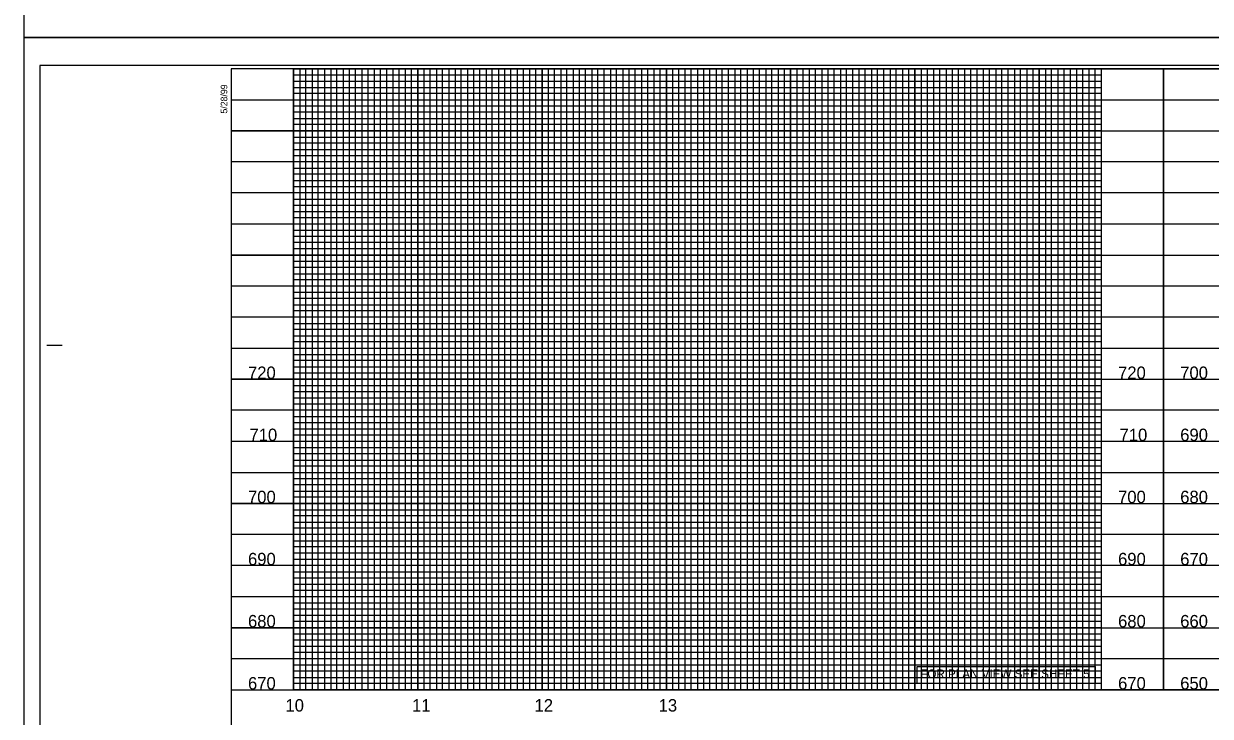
# Model space of a CAD drawing. Extents: x 1754992 to 1757273, y 732111 to 735411.
# Drawn here: x 1755181 to 1756135, y 732664 to 733222 of the extents above; entities that cross this region are included whole.
import ezdxf

# ---------------------------------------------------------------- set-up
doc = ezdxf.new("R2010")
doc.units = 0
for name, color, linetype in [('ENG SEALS CELL', 7, 'Continuous'), ('Prop DSN Text', 7, 'Continuous'), ('Scratch_Level_3', 7, 'Continuous'), ('Sheet Cutting Line CELL', 7, 'Continuous'), ('Sheet DOT Grid CELL', 7, 'Continuous'), ('Sheet PE Seal Cell', 7, 'Continuous'), ('Sheet Plot Border Inside CELL', 7, 'Continuous'), ('Sheet Plot Border Outside CELL', 7, 'Continuous'), ('Sheet Profile CELL', 7, 'Continuous'), ('Sheet Profile Grid Major CELL', 7, 'Continuous'), ('Sheet Profile Grid Middle CELL', 7, 'Continuous'), ('Sheet Profile Grid Minor CELL', 7, 'Continuous')]:
    doc.layers.add(name, color=color, linetype=linetype)

msp = doc.modelspace()

# ---------------------------------------------------------------- linework, layer by layer
at = {"layer": 'ENG SEALS CELL'}
msp.add_lwpolyline([(1755899.57, 732704.63), (1756042.57, 732704.63), (1756042.57, 732690.9), (1755899.57, 732690.9)], close=True, dxfattribs=at)
at = {"layer": 'Scratch_Level_3'}
msp.add_lwpolyline([(1755397.67, 732685.78), (1755397.67, 733185.78), (1756647.62, 733185.78), (1756647.63, 732952.66), (1756797.67, 732952.66), (1756797.67, 732685.78)], close=True, dxfattribs=at)
at = {"layer": 'Sheet Cutting Line CELL'}
for p, q in [((1755180.67, 734310.78), (1755180.67, 733210.78)), ((1756864.67, 733210.78), (1755180.67, 733210.78)), ((1755180.67, 733210.78), (1755180.67, 732110.78)), ((1755180.67, 733210.78), (1756864.67, 733210.78))]:
    msp.add_line(p, q, dxfattribs=at)
at = {"layer": 'Sheet DOT Grid CELL'}
for p, q in [((1755397.67, 732685.78), (1755397.67, 733185.78)), ((1755447.67, 732685.78), (1755447.67, 733185.78)), ((1755497.67, 732685.78), (1755497.67, 733185.78)), ((1755547.67, 732685.78), (1755547.67, 733185.78)), ((1755597.67, 732685.78), (1755597.67, 733185.78)), ((1755647.67, 732685.78), (1755647.67, 733185.78)), ((1755697.67, 732685.78), (1755697.67, 733185.78)), ((1755747.67, 732685.78), (1755747.67, 733185.78)), ((1755797.67, 732685.78), (1755797.67, 733185.78)), ((1755847.67, 732685.78), (1755847.67, 733185.78)), ((1755897.67, 732685.78), (1755897.67, 733185.78)), ((1755947.67, 732685.78), (1755947.67, 733185.78)), ((1755997.67, 732685.78), (1755997.67, 733185.78)), ((1756047.67, 732685.78), (1756047.67, 733185.78)), ((1756097.67, 732685.78), (1756097.67, 733185.78)), ((1756047.68, 733135.78), (1755347.67, 733135.78)), ((1756047.68, 733085.78), (1755347.67, 733085.78)), ((1756047.68, 733035.78), (1755347.67, 733035.78)), ((1756047.68, 732985.78), (1755347.67, 732985.78)), ((1756047.68, 732935.78), (1755347.67, 732935.78)), ((1756047.68, 732885.78), (1755347.67, 732885.78)), ((1756047.68, 732835.78), (1755347.67, 732835.78)), ((1756047.68, 732785.78), (1755347.67, 732785.78)), ((1756047.68, 732735.78), (1755347.67, 732735.78))]:
    msp.add_line(p, q, dxfattribs=at)
at = {"layer": 'Sheet Plot Border Inside CELL'}
msp.add_lwpolyline([(1755193.67, 732133.23), (1756860.17, 732133.23), (1756860.17, 733188.33), (1755193.67, 733188.33)], close=True, dxfattribs=at)
at = {"layer": 'Sheet Plot Border Outside CELL'}
for points in [[(1755180.67, 733210.78), (1756864.67, 733210.78), (1756864.67, 734310.78), (1755180.67, 734310.78)], [(1755180.67, 732110.78), (1756864.67, 732110.78), (1756864.67, 733210.78), (1755180.67, 733210.78)]]:
    msp.add_lwpolyline(points, close=True, dxfattribs=at)
at = {"layer": 'Sheet Profile CELL'}
for p, q in [((1756097.67, 733185.78), (1756097.67, 732685.78)), ((1755199.17, 732963.28), (1755211.67, 732963.28)), ((1755347.67, 732685.78), (1756847.67, 732685.78))]:
    msp.add_line(p, q, dxfattribs=at)
msp.add_lwpolyline([(1756847.67, 733185.78), (1755347.67, 733185.78), (1755347.67, 732135.78), (1756847.67, 732135.78)], close=True, dxfattribs=at)
at = {"layer": 'Sheet Profile Grid Major CELL'}
for points in [[(1755397.67, 733185.78), (1755397.67, 732685.78), (1755447.67, 732685.78), (1755447.67, 733185.78), (1755497.67, 733185.78), (1755497.67, 732685.78), (1755547.67, 732685.78), (1755547.67, 733185.78), (1755597.67, 733185.78), (1755597.67, 732685.78), (1755647.67, 732685.78), (1755647.67, 733185.78), (1755697.67, 733185.78), (1755697.67, 732685.78), (1755747.67, 732685.78), (1755747.67, 733185.78), (1755797.67, 733185.78), (1755797.67, 732685.78), (1755847.67, 732685.78), (1755847.67, 733185.78), (1755897.67, 733185.78), (1755897.67, 732685.78), (1755947.67, 732685.78), (1755947.67, 733185.78), (1755997.67, 733185.78), (1755997.67, 732685.78), (1756047.67, 732685.78), (1756047.67, 733185.78), (1756097.67, 733185.78), (1756097.67, 732685.78), (1756147.67, 732685.78)], [(1755347.67, 733135.78), (1756647.67, 733135.78)], [(1756647.67, 733085.78), (1755347.67, 733085.78), (1755347.67, 733035.78), (1756647.67, 733035.78)], [(1756647.63, 732985.78), (1755347.67, 732985.78), (1755347.67, 732935.78), (1756847.67, 732935.78)], [(1756847.67, 732885.78), (1755347.67, 732885.78), (1755347.67, 732835.78), (1756847.67, 732835.78)], [(1756847.67, 732785.78), (1755347.67, 732785.78), (1755347.67, 732785.78), (1755347.67, 732735.78), (1756847.67, 732735.78)]]:
    msp.add_lwpolyline(points, dxfattribs=at)
at = {"layer": 'Sheet Profile Grid Middle CELL'}
for p, q in [((1755422.67, 733185.78), (1755422.67, 732685.78)), ((1755472.67, 732685.78), (1755472.67, 733185.78)), ((1755472.67, 733185.78), (1755522.67, 733185.78)), ((1755522.67, 733185.78), (1755522.67, 732685.78)), ((1755572.67, 732685.78), (1755572.67, 733185.78)), ((1755572.67, 733185.78), (1755622.67, 733185.78)), ((1755622.67, 733185.78), (1755622.67, 732685.78)), ((1755672.67, 732685.78), (1755672.67, 733185.78)), ((1755672.67, 733185.78), (1755722.67, 733185.78)), ((1755722.67, 733185.78), (1755722.67, 732685.78)), ((1755772.67, 732685.78), (1755772.67, 733185.78)), ((1755772.67, 733185.78), (1755822.67, 733185.78)), ((1755822.67, 733185.78), (1755822.67, 732685.78)), ((1755872.67, 732685.78), (1755872.67, 733185.78)), ((1755872.67, 733185.78), (1755922.67, 733185.78)), ((1755922.67, 733185.78), (1755922.67, 732685.78)), ((1755972.67, 732685.78), (1755972.67, 733185.78)), ((1755972.67, 733185.78), (1756022.67, 733185.78)), ((1756022.67, 733185.78), (1756022.67, 732685.78)), ((1756072.67, 733185.78), (1756122.67, 733185.78)), ((1755347.67, 733160.78), (1756647.62, 733160.78)), ((1755422.67, 732685.78), (1755472.67, 732685.78)), ((1755522.67, 732685.78), (1755572.67, 732685.78)), ((1755622.67, 732685.78), (1755672.67, 732685.78)), ((1755722.67, 732685.78), (1755772.67, 732685.78)), ((1755822.67, 732685.78), (1755872.67, 732685.78)), ((1755922.67, 732685.78), (1755972.67, 732685.78)), ((1755972.67, 732685.78), (1755972.67, 732685.78)), ((1756022.67, 732685.78), (1756072.67, 732685.78)), ((1756122.67, 732685.78), (1756172.67, 732685.78))]:
    msp.add_line(p, q, dxfattribs=at)
for points in [[(1756647.67, 733110.78), (1755347.67, 733110.78), (1755347.67, 733060.78), (1756647.67, 733060.78)], [(1756647.62, 733010.78), (1755347.67, 733010.78), (1755347.67, 732960.78), (1756647.63, 732960.78)], [(1756847.67, 732910.78), (1755347.67, 732910.78), (1755347.67, 732860.78), (1756847.67, 732860.78)], [(1756847.67, 732810.78), (1755347.67, 732810.78), (1755347.67, 732760.78), (1756847.67, 732760.78)], [(1756847.67, 732710.78), (1755347.67, 732710.78)]]:
    msp.add_lwpolyline(points, dxfattribs=at)
at = {"layer": 'Sheet Profile Grid Minor CELL'}
for p, q in [((1755397.67, 733180.78), (1756047.68, 733180.78)), ((1755927.67, 733185.78), (1755927.67, 732685.78)), ((1755932.67, 732685.78), (1755932.67, 733185.78)), ((1755932.67, 733185.78), (1755937.67, 733185.78)), ((1755937.67, 733185.78), (1755937.67, 732685.78)), ((1755942.67, 732685.78), (1755942.67, 733185.78)), ((1755942.67, 733185.78), (1755952.67, 733185.78)), ((1755952.67, 733185.78), (1755952.67, 732685.78)), ((1755957.67, 732685.78), (1755957.67, 733185.78)), ((1755957.67, 733185.78), (1755962.67, 733185.78)), ((1755962.67, 733185.78), (1755962.67, 732685.78)), ((1755967.67, 732685.78), (1755967.67, 733185.78)), ((1755967.67, 733185.78), (1755977.67, 733185.78)), ((1755977.67, 733185.78), (1755977.67, 732685.78)), ((1755982.67, 732685.78), (1755982.67, 733185.78)), ((1755982.67, 733185.78), (1755987.67, 733185.78)), ((1755987.67, 733185.78), (1755987.67, 732685.78)), ((1755992.67, 732685.78), (1755992.67, 733185.78)), ((1755992.67, 733185.78), (1756002.67, 733185.78)), ((1756002.67, 733185.78), (1756002.67, 732685.78)), ((1756007.67, 732685.78), (1756007.67, 733185.78)), ((1756007.67, 733185.78), (1756012.67, 733185.78)), ((1756012.67, 733185.78), (1756012.67, 732685.78)), ((1756017.67, 732685.78), (1756017.67, 733185.78)), ((1756017.67, 733185.78), (1756027.67, 733185.78)), ((1756027.67, 733185.78), (1756027.67, 732685.78)), ((1756032.67, 732685.78), (1756032.67, 733185.78)), ((1756032.67, 733185.78), (1756037.67, 733185.78)), ((1756037.67, 733185.78), (1756037.67, 732685.78)), ((1756042.67, 732685.78), (1756042.67, 733185.78)), ((1756042.67, 733185.78), (1756052.67, 733185.78)), ((1756057.67, 733185.78), (1756062.67, 733185.78)), ((1756067.67, 733185.78), (1756077.67, 733185.78)), ((1756082.67, 733185.78), (1756087.67, 733185.78)), ((1756092.67, 733185.78), (1756102.67, 733185.78)), ((1756107.67, 733185.78), (1756112.67, 733185.78)), ((1756117.67, 733185.78), (1756127.67, 733185.78)), ((1756132.67, 733185.78), (1756137.67, 733185.78)), ((1755397.67, 733175.78), (1755397.67, 733175.78)), ((1756047.68, 733175.62), (1755397.67, 733175.43)), ((1755397.67, 733170.78), (1756047.68, 733170.78)), ((1756047.68, 733050.78), (1755397.67, 733050.78)), ((1756047.68, 733045.78), (1755397.67, 733045.78)), ((1756047.68, 733040.78), (1755397.67, 733040.78)), ((1755397.67, 733030.78), (1756047.68, 733030.78)), ((1756047.68, 733025.78), (1755397.67, 733025.78)), ((1755397.67, 733020.78), (1756047.68, 733020.78)), ((1756047.68, 733000.78), (1755397.67, 733000.78)), ((1755397.67, 732995.78), (1756047.68, 732995.78)), ((1756047.68, 732975.78), (1755397.67, 732975.78)), ((1755397.67, 732970.78), (1756047.68, 732970.78)), ((1756047.68, 732950.78), (1755397.67, 732950.78)), ((1755397.67, 732945.78), (1756047.68, 732945.78)), ((1756047.68, 732940.78), (1755397.67, 732940.78)), ((1755397.67, 732930.78), (1756047.68, 732930.78)), ((1756047.68, 732925.78), (1755397.67, 732925.78)), ((1755397.67, 732920.78), (1756047.68, 732920.78)), ((1756047.68, 732915.78), (1755397.67, 732915.78)), ((1755397.67, 732905.78), (1756047.68, 732905.78)), ((1756047.68, 732900.78), (1755397.67, 732900.78)), ((1755397.67, 732895.78), (1756047.68, 732895.78)), ((1756047.68, 732890.78), (1755397.67, 732890.78)), ((1755397.67, 732880.78), (1756047.68, 732880.78)), ((1756047.68, 732875.78), (1755397.67, 732875.78)), ((1755397.67, 732870.78), (1756047.68, 732870.78)), ((1756047.68, 732865.78), (1755397.67, 732865.78)), ((1755397.67, 732855.78), (1756047.68, 732855.78)), ((1756047.68, 732850.78), (1755397.67, 732850.78)), ((1755397.67, 732845.78), (1756047.68, 732845.78)), ((1756047.68, 732840.78), (1755397.67, 732840.78)), ((1755397.67, 732830.78), (1756047.68, 732830.78)), ((1756047.68, 732825.78), (1755397.67, 732825.78)), ((1755397.67, 732820.78), (1756047.68, 732820.78)), ((1756047.68, 732815.78), (1755397.67, 732815.78)), ((1755397.67, 732805.78), (1756047.68, 732805.78)), ((1756047.68, 732800.78), (1755397.67, 732800.78)), ((1756047.68, 732795.78), (1755397.67, 732795.78)), ((1756047.68, 732790.78), (1755397.67, 732790.78)), ((1755397.67, 732780.78), (1756047.68, 732780.78)), ((1756047.68, 732775.78), (1755397.67, 732775.78)), ((1755397.67, 732770.78), (1756047.68, 732770.78)), ((1756047.68, 732765.78), (1755397.67, 732765.78)), ((1755397.67, 732755.78), (1756047.68, 732755.78)), ((1756047.68, 732750.78), (1755397.67, 732750.78)), ((1755397.67, 732745.78), (1756047.68, 732745.78)), ((1756047.68, 732740.78), (1755397.67, 732740.78)), ((1755397.67, 732730.78), (1756047.68, 732730.78)), ((1756047.68, 732725.78), (1755397.67, 732725.78)), ((1755397.67, 732720.78), (1756047.68, 732720.78)), ((1756047.68, 732715.78), (1755397.67, 732715.78)), ((1755397.67, 732705.78), (1756047.68, 732705.78)), ((1756047.68, 732700.78), (1755397.67, 732700.78)), ((1755397.67, 732695.78), (1756047.68, 732695.78)), ((1755927.67, 732685.78), (1755932.67, 732685.78)), ((1755937.67, 732685.78), (1755942.67, 732685.78)), ((1755952.67, 732685.78), (1755957.67, 732685.78)), ((1755962.67, 732685.78), (1755967.67, 732685.78)), ((1755977.67, 732685.78), (1755982.67, 732685.78)), ((1755987.67, 732685.78), (1755992.67, 732685.78)), ((1756002.67, 732685.78), (1756007.67, 732685.78)), ((1756012.67, 732685.78), (1756017.67, 732685.78)), ((1756027.67, 732685.78), (1756032.67, 732685.78)), ((1756037.67, 732685.78), (1756042.67, 732685.78)), ((1756052.67, 732685.78), (1756052.67, 732685.78)), ((1756052.67, 732685.78), (1756057.67, 732685.78)), ((1756062.67, 732685.78), (1756067.67, 732685.78)), ((1756077.67, 732685.78), (1756082.67, 732685.78)), ((1756087.67, 732685.78), (1756092.67, 732685.78)), ((1756102.67, 732685.78), (1756107.67, 732685.78)), ((1756112.67, 732685.78), (1756117.67, 732685.78)), ((1756127.67, 732685.78), (1756132.67, 732685.78))]:
    msp.add_line(p, q, dxfattribs=at)
for points in [[(1755402.67, 733185.78), (1755402.67, 732685.78), (1755407.67, 732685.78), (1755407.67, 733185.78), (1755412.67, 733185.78), (1755412.67, 732685.78), (1755417.67, 732685.78), (1755417.67, 733185.78), (1755427.67, 733185.78), (1755427.67, 732685.78), (1755432.67, 732685.78), (1755432.67, 733185.78), (1755437.67, 733185.78), (1755437.67, 732685.78), (1755442.67, 732685.78), (1755452.67, 732685.78), (1755457.67, 732685.78), (1755457.67, 733185.78), (1755462.67, 733185.78), (1755462.67, 732685.78), (1755467.67, 732685.78), (1755467.67, 733185.78), (1755477.67, 733185.78), (1755477.67, 732685.78), (1755482.67, 732685.78), (1755482.67, 733185.78), (1755487.67, 733185.78), (1755487.67, 732685.78), (1755492.67, 732685.78), (1755492.67, 733185.78), (1755502.67, 733185.78), (1755502.67, 732685.78), (1755507.67, 732685.78), (1755507.67, 733185.78), (1755512.67, 733185.78), (1755512.67, 732685.78), (1755517.67, 732685.78), (1755517.67, 733185.78), (1755527.67, 733185.78), (1755527.67, 732685.78), (1755532.67, 732685.78), (1755532.67, 733185.78), (1755537.67, 733185.78), (1755537.67, 732685.78), (1755542.67, 732685.78), (1755542.67, 733185.78), (1755552.67, 733185.78), (1755552.67, 732685.78), (1755557.67, 732685.78), (1755557.67, 733185.78), (1755562.67, 733185.78), (1755562.67, 732685.78), (1755567.67, 732685.78), (1755567.67, 733185.78), (1755577.67, 733185.78), (1755577.67, 732685.78), (1755582.67, 732685.78), (1755582.67, 733185.78), (1755587.67, 733185.78), (1755587.67, 732685.78), (1755592.67, 732685.78), (1755592.67, 733185.78), (1755602.67, 733185.78), (1755602.67, 732685.78), (1755607.67, 732685.78), (1755607.67, 733185.78), (1755612.67, 733185.78), (1755612.67, 732685.78)], [(1755442.67, 732685.78), (1755442.67, 733185.78), (1755452.67, 733185.78), (1755452.67, 732685.78)], [(1755612.67, 732685.78), (1755617.67, 732685.78), (1755617.67, 733185.78), (1755627.67, 733185.78), (1755627.67, 732685.78), (1755632.67, 732685.78), (1755632.67, 733185.78), (1755637.67, 733185.78), (1755637.67, 732685.78), (1755642.67, 732685.78), (1755642.67, 733185.78), (1755652.67, 733185.78), (1755652.67, 732685.78), (1755657.67, 732685.78), (1755657.67, 733185.78), (1755662.67, 733185.78), (1755662.67, 732685.78), (1755667.67, 732685.78), (1755667.67, 733185.78), (1755677.67, 733185.78), (1755677.67, 732685.78), (1755682.67, 732685.78), (1755682.67, 733185.78), (1755687.67, 733185.78), (1755687.67, 732685.78), (1755692.67, 732685.78), (1755692.67, 733185.78), (1755702.67, 733185.78), (1755702.67, 732685.78), (1755707.67, 732685.78), (1755707.67, 733185.78), (1755712.67, 733185.78), (1755712.67, 732685.78), (1755717.67, 732685.78), (1755717.67, 733185.78), (1755727.67, 733185.78), (1755727.67, 732685.78), (1755732.67, 732685.78), (1755732.67, 733185.78), (1755737.67, 733185.78), (1755737.67, 732685.78), (1755742.67, 732685.78), (1755742.67, 733185.78), (1755752.67, 733185.78), (1755752.67, 732685.78), (1755757.67, 732685.78), (1755757.67, 733185.78), (1755762.67, 733185.78), (1755762.67, 732685.78), (1755767.67, 732685.78), (1755767.67, 733185.78), (1755777.67, 733185.78), (1755777.67, 732685.78), (1755782.67, 732685.78), (1755782.67, 733185.78), (1755787.67, 733185.78), (1755787.67, 732685.78), (1755792.67, 732685.78), (1755792.67, 733185.78), (1755802.67, 733185.78), (1755802.67, 732685.78), (1755807.67, 732685.78), (1755807.67, 733185.78), (1755812.67, 733185.78), (1755812.67, 732685.78), (1755817.67, 732685.78), (1755817.67, 733185.78), (1755827.67, 733185.78), (1755827.67, 732685.78), (1755832.67, 732685.78), (1755832.67, 733185.78), (1755837.67, 733185.78), (1755837.67, 732685.78), (1755842.67, 732685.78), (1755842.67, 733185.78), (1755852.67, 733185.78), (1755852.67, 732685.78), (1755857.67, 732685.78), (1755857.67, 733185.78), (1755862.67, 733185.78), (1755862.67, 732685.78), (1755867.67, 732685.78), (1755867.67, 733185.78), (1755877.67, 733185.78), (1755877.67, 732685.78), (1755882.67, 732685.78), (1755882.67, 733185.78), (1755887.67, 733185.78), (1755887.67, 732685.78), (1755892.67, 732685.78), (1755892.67, 733185.78), (1755902.67, 733185.78), (1755902.67, 732685.78), (1755907.67, 732685.78), (1755907.67, 733185.78), (1755912.67, 733185.78), (1755912.67, 732685.78), (1755917.67, 732685.78), (1755917.67, 733185.78), (1755927.67, 733185.78)], [(1756047.68, 733165.78), (1755397.67, 733165.78), (1755397.67, 733155.78), (1756047.68, 733155.78)], [(1756047.68, 733150.78), (1755397.67, 733150.78), (1755397.67, 733145.78), (1756047.68, 733145.78)], [(1756047.68, 733140.78), (1755397.67, 733140.78), (1755397.67, 733130.78), (1756047.68, 733130.78)], [(1756047.68, 733125.78), (1755397.67, 733125.78), (1755397.67, 733120.78), (1756047.68, 733120.78)], [(1756047.68, 733115.78), (1755397.67, 733115.78), (1755397.67, 733105.78), (1756047.68, 733105.78)], [(1756047.68, 733100.78), (1755397.67, 733100.78), (1755397.67, 733095.78), (1756047.68, 733095.78)], [(1756047.68, 733090.78), (1755397.67, 733090.78), (1755397.67, 733080.78), (1756047.68, 733080.78)], [(1756047.68, 733075.68), (1755397.77, 733075.68), (1755397.77, 733070.78), (1756047.68, 733070.78)], [(1756047.68, 733065.78), (1755397.67, 733065.78), (1755397.67, 733055.78), (1756047.68, 733055.78)], [(1756047.68, 733015.78), (1755397.67, 733015.78), (1755397.67, 733005.78), (1756047.68, 733005.78)], [(1756047.68, 732990.78), (1755397.67, 732990.78), (1755397.67, 732980.78), (1756047.68, 732980.78)], [(1756047.68, 732965.78), (1755397.67, 732965.78), (1755397.67, 732955.78), (1756047.68, 732955.78)], [(1756047.68, 732690.78), (1755397.67, 732690.78)]]:
    msp.add_lwpolyline(points, dxfattribs=at)

# ---------------------------------------------------------------- texts
at = {"layer": 'Prop DSN Text'}
for s, p in [('720', (1755361.1, 732936.03)), ('720', (1756061.1, 732936.03)), ('720', (1756061.1, 732936.03)), ('700', (1756111.1, 732936.03)), ('710', (1755362.3, 732886.03)), ('710', (1756062.3, 732886.03)), ('710', (1756062.3, 732886.03)), ('690', (1756111.1, 732886.03)), ('700', (1755361.1, 732836.03)), ('700', (1756061.1, 732836.03)), ('700', (1756061.1, 732836.03)), ('680', (1756111.1, 732836.03)), ('690', (1755361.1, 732786.03)), ('690', (1756061.1, 732786.03)), ('670', (1756111.1, 732786.03)), ('680', (1755361.1, 732736.03)), ('680', (1756061.1, 732736.03)), ('660', (1756111.1, 732736.03)), ('670', (1755361.1, 732686.03)), ('670', (1756061.1, 732686.03)), ('650', (1756111.1, 732686.03))]:
    msp.add_text(s, height=10, dxfattribs=at).set_placement(p)
at = {"layer": 'Scratch_Level_3'}
for s, p in [('10', (1755391.25, 732668.28)), ('11', (1755493.09, 732668.28)), ('12', (1755591.64, 732668.28)), ('13', (1755691.48, 732668.28))]:
    msp.add_text(s, height=10, dxfattribs=at).set_placement(p)
at = {"layer": 'Sheet PE Seal Cell'}
msp.add_text('FOR PLAN VIEW SEE SHEET 5', height=7, dxfattribs=at).set_placement((1755901.97, 732695.14))
at = {"layer": 'Sheet Profile CELL'}
msp.add_text('5/28/99', height=5.25, rotation=90, dxfattribs=at).set_placement((1755344.43, 733149.7))

doc.saveas('drawing.dxf')
